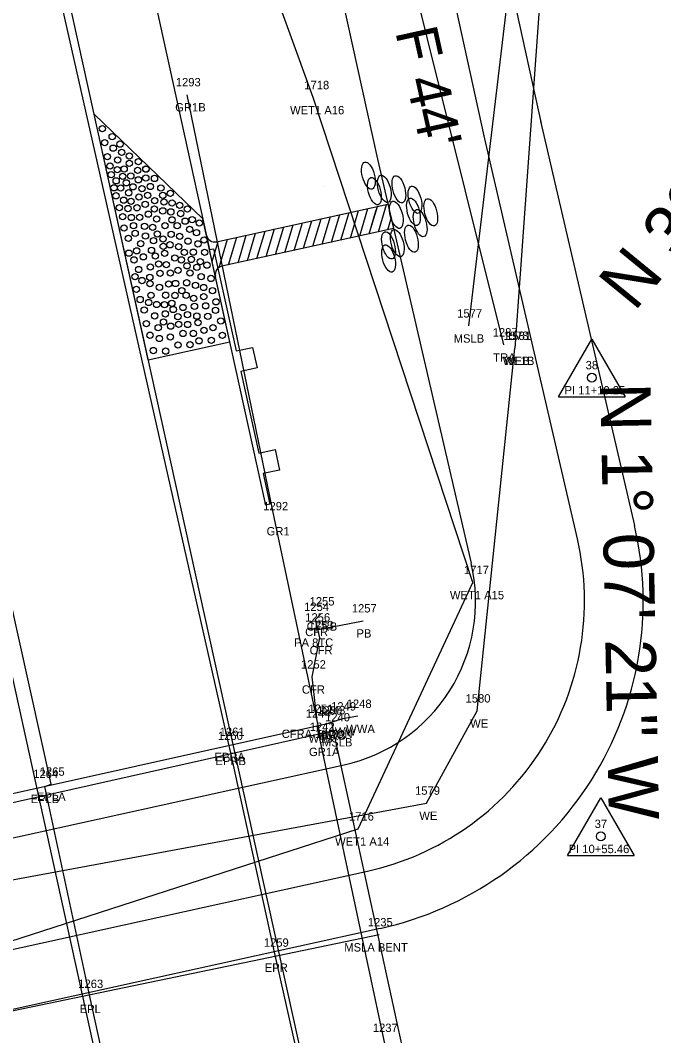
# Model space of a CAD drawing. Extents: x 2521558 to 2525396, y 882711 to 887632.
# Drawn here: x 2523767.9 to 2523844.7, y 885124.5 to 885245.8 of the extents above; entities that cross this region are included whole.
import ezdxf

# ---------------------------------------------------------------- set-up
doc = ezdxf.new("R2010")
doc.units = 0
for name, color, linetype in [('RD_EV_JurisArea', 7, 'Continuous'), ('RD_EX_BldgApp', 7, 'Continuous'), ('RD_EX_BldgApp_txCode', 7, 'Continuous'), ('RD_EX_Bridge', 7, 'Continuous'), ('RD_EX_Bridge_txCode', 7, 'Continuous'), ('RD_EX_Conc', 7, 'Continuous'), ('RD_EX_Conc_txCode', 7, 'Continuous'), ('RD_EX_DR_Pipe', 7, 'Continuous'), ('RD_EX_DR_Pipe_txCode', 7, 'Continuous'), ('RD_EX_GuardRail', 7, 'Continuous'), ('RD_EX_GuardRail_txCode', 7, 'Continuous'), ('RD_EX_H2O', 7, 'Continuous'), ('RD_EX_H2O_txCode', 7, 'Continuous'), ('RD_EX_H2O_WetLd_txCode', 7, 'Continuous'), ('RD_EX_Misc', 7, 'Continuous'), ('RD_EX_Misc_txCode', 7, 'Continuous'), ('RD_EX_Road', 7, 'Continuous'), ('RD_EX_Road_txCode', 7, 'Continuous'), ('RD_EX_VEG', 7, 'Continuous'), ('RD_EX_VEG_txCode', 7, 'Continuous'), ('RD_HC_Data', 7, 'Continuous'), ('RD_HC_txCode', 7, 'Continuous'), ('RD_PD_BCA', 7, 'Continuous'), ('RD_PD_Bridge', 7, 'Continuous'), ('RD_PD_CstnLmt', 7, 'Continuous'), ('RD_PD_DR_ErosCtrl', 7, 'Continuous'), ('RD_PD_Final_TrvlWay', 7, 'Continuous'), ('RD_PD_GR', 7, 'Continuous'), ('RD_PD_PaveShd', 7, 'Continuous'), ('RD_SMD_Locator', 7, 'Continuous')]:
    doc.layers.add(name, color=color, linetype=linetype)

# ---------------------------------------------------------------- blocks, each defined once
blk = doc.blocks.new('TBC1')
at = {"layer": 'RD_PD_GR'}
blk.add_lwpolyline([(12.5, 2.5), (15, 2.5), (15, 0.49), (25, 0.49), (25, 2.5), (27.5, 2.5), (27.5, 0.49), (31.25, 0.49), (31.25, 0), (0, 0), (0, 0.49), (12.5, 0.49)], close=True, dxfattribs=at)

msp = doc.modelspace()

# ---------------------------------------------------------------- linework, layer by layer
at = {"layer": 'RD_EV_JurisArea'}
msp.add_lwpolyline([(2523761.17, 885134.03), (2523808.21, 885149.21), (2523821.91, 885178.64), (2523802.85, 885236.55), (2523777.81, 885305.56), (2523748.2, 885444.32), (2523730.68, 885516.88), (2523708.64, 885617.3), (2523698.71, 885662.02), (2523727.83, 885665.82), (2523757.3, 885671.75)], dxfattribs=at)
at = {"layer": 'RD_EX_BldgApp'}
msp.add_lwpolyline([(2523819.44, 885087.44), (2523811.32, 885123.96), (2523803.31, 885161.5)], dxfattribs=at)
at = {"layer": 'RD_EX_Bridge'}
for points in [[(2523774.91, 885077.6), (2523821.2, 885087.83), (2523805.06, 885161.89), (2523758.15, 885151.44), (2523774.91, 885077.6)], [(2523808.19, 885162.66), (2523806.34, 885162.35), (2523804.71, 885161.86)]]:
    msp.add_lwpolyline(points, dxfattribs=at)
at = {"layer": 'RD_EX_Conc'}
msp.add_lwpolyline([(2523803.34, 885162.07), (2523802.73, 885167.36), (2523803.65, 885172.05), (2523803.12, 885174.24), (2523803.77, 885174.89)], dxfattribs=at)
at = {"layer": 'RD_EX_DR_Pipe'}
msp.add_line((2523803.27, 885172.97), (2523808.8, 885174.06), dxfattribs=at)
at = {"layer": 'RD_EX_GuardRail'}
msp.add_lwpolyline([(2523803.79, 885159.91), (2523798.24, 885186.26), (2523787.8, 885236.89)], dxfattribs=at)
at = {"layer": 'RD_EX_H2O'}
for points in [[(2524064.86, 885165.15), (2524036.37, 885213.78), (2524057.22, 885252.72), (2524031.95, 885291.63), (2523983.25, 885326.3), (2523940.61, 885311.83), (2523904.84, 885305.01), (2523874.98, 885272.1), (2523850.32, 885280.24), (2523830.66, 885258.8), (2523826.93, 885206.61)], [(2523738.91, 885147.5), (2523743.69, 885138.84), (2523816.36, 885152.29), (2523822.43, 885163.3), (2523826.93, 885206.61)]]:
    msp.add_lwpolyline(points, dxfattribs=at)
at = {"layer": 'RD_EX_Misc'}
for p, q in [((2523758.45, 885150.47), (2523805.66, 885161.06)), ((2523810.71, 885136.57), (2523763.83, 885126.8))]:
    msp.add_line(p, q, dxfattribs=at)
msp.add_lwpolyline([(2524066.31, 885165.35), (2524037.3, 885214.15), (2524057.95, 885253.07), (2524039.52, 885283.17), (2524032.92, 885292.57), (2523983.53, 885327.98), (2523940.24, 885313.27), (2523904.13, 885306.25), (2523874.86, 885272.67), (2523849.96, 885282.51), (2523827.65, 885261.93), (2523821.38, 885209.28)], dxfattribs=at)
at = {"layer": 'RD_EX_Road'}
for p, q in [((2523792.78, 885159.31), (2523771.24, 885254.79)), ((2523771.58, 885154.56), (2523750.32, 885250.18)), ((2523792.89, 885158.83), (2523792.78, 885159.31)), ((2523798.3, 885134.14), (2523792.89, 885158.83)), ((2523770.8, 885154.29), (2523771.58, 885154.56)), ((2523776.18, 885129.21), (2523770.8, 885154.29)), ((2523803.79, 885109.94), (2523798.3, 885134.14)), ((2523781.52, 885104.77), (2523776.18, 885129.21))]:
    msp.add_line(p, q, dxfattribs=at)
at = {"layer": 'RD_EX_VEG'}
msp.add_lwpolyline([(2523825.62, 885207.01), (2523811.87, 885262.11), (2523733.02, 885654.22), (2523687.11, 885876.24)], dxfattribs=at)
at = {"layer": 'RD_HC_Data'}
for p, q in [((2523832.14, 885200.81), (2523836.11, 885207.69)), ((2523836.11, 885207.69), (2523840.08, 885200.81)), ((2523832.14, 885200.81), (2523840.08, 885200.81)), ((2523833.21, 885146.03), (2523837.18, 885152.91)), ((2523837.18, 885152.91), (2523841.15, 885146.03)), ((2523833.21, 885146.03), (2523841.15, 885146.03))]:
    msp.add_line(p, q, dxfattribs=at)
for centre in [(2523836.11, 885203.1), (2523837.18, 885148.32)]:
    msp.add_circle(centre, 0.529, dxfattribs=at)
at = {"layer": 'RD_PD_BCA'}
for p, q in [((2523824.7, 885257.92), (2523830.05, 885233.47)), ((2523829.99, 885233.72), (2523841.2, 885185.45))]:
    msp.add_line(p, q, dxfattribs=at)
msp.add_lwpolyline([(2523762.05, 885126.6), (2523810.84, 885137.34)], dxfattribs=at)
msp.add_arc((2523802.24, 885176.4), 40, 282.4185, 13.0724, dxfattribs=at)
at = {"layer": 'RD_PD_CstnLmt'}
for p, q in [((2523789.14, 885326.89), (2523810.51, 885229.2)), ((2523810.51, 885229.2), (2523821.72, 885180.93))]:
    msp.add_line(p, q, dxfattribs=at)
msp.add_lwpolyline([(2523757.75, 885146.13), (2523806.54, 885156.87)], dxfattribs=at)
msp.add_arc((2523802.24, 885176.4), 20, 282.4185, 13.0724, dxfattribs=at)
at = {"layer": 'RD_PD_DR_ErosCtrl'}
for p, q in [((2523801.84, 885329.66), (2523823.21, 885231.97)), ((2523823.17, 885232.14), (2523834.38, 885183.87))]:
    msp.add_line(p, q, dxfattribs=at)
msp.add_lwpolyline([(2523760.55, 885133.43), (2523809.33, 885144.17)], dxfattribs=at)
msp.add_arc((2523802.24, 885176.4), 33, 282.4185, 13.0724, dxfattribs=at)
at = {"layer": 'RD_PD_Final_TrvlWay'}
for p, q in [((2523720.24, 885490.91), (2524037.44, 884050.42)), ((2523696.8, 885485.75), (2524014, 884045.26))]:
    msp.add_line(p, q, dxfattribs=at)
at = {"layer": 'RD_PD_GR'}
msp.add_line((2523742.1, 885438.13), (2523790.49, 885218.39), dxfattribs=at)
at = {"layer": 'RD_PD_PaveShd'}
for p, q in [((2523776.69, 885234.55), (2523789.68, 885222.05)), ((2523783.14, 885205.25), (2523776.69, 885234.55)), ((2523791.3, 885219.34), (2523811.76, 885223.83)), ((2523810.64, 885220.51), (2523811.62, 885223.8)), ((2523810.64, 885220.51), (2523811.62, 885223.8)), ((2523811.76, 885223.83), (2523812.44, 885220.91)), ((2523805.05, 885219.29), (2523806.04, 885222.57)), ((2523805.05, 885219.29), (2523806.04, 885222.57)), ((2523806.17, 885219.53), (2523807.15, 885222.82)), ((2523806.17, 885219.53), (2523807.03, 885222.41)), ((2523807.29, 885219.78), (2523808.27, 885223.06)), ((2523807.29, 885219.78), (2523808.27, 885223.06)), ((2523808.4, 885220.02), (2523809.39, 885223.31)), ((2523808.4, 885220.02), (2523809.39, 885223.31)), ((2523809.52, 885220.27), (2523810.51, 885223.55)), ((2523809.52, 885220.27), (2523810.38, 885223.15)), ((2523790.33, 885219.12), (2523789.68, 885222.05)), ((2523799.47, 885218.06), (2523800.45, 885221.35)), ((2523799.47, 885218.06), (2523800.45, 885221.35)), ((2523800.58, 885218.3), (2523801.57, 885221.59)), ((2523800.58, 885218.3), (2523801.57, 885221.59)), ((2523801.7, 885218.55), (2523802.68, 885221.84)), ((2523801.7, 885218.55), (2523802.68, 885221.84)), ((2523802.82, 885218.79), (2523803.8, 885222.08)), ((2523802.82, 885218.79), (2523803.8, 885222.08)), ((2523803.93, 885219.04), (2523804.92, 885222.33)), ((2523803.93, 885219.04), (2523804.92, 885222.33)), ((2523811.76, 885220.76), (2523812.16, 885222.1)), ((2523811.76, 885220.76), (2523812.16, 885222.1)), ((2523812.44, 885220.91), (2523791.95, 885216.41)), ((2523793.88, 885216.83), (2523794.86, 885220.12)), ((2523793.88, 885216.83), (2523794.86, 885220.12)), ((2523795, 885217.08), (2523795.98, 885220.36)), ((2523795, 885217.08), (2523795.98, 885220.36)), ((2523796.11, 885217.32), (2523797.1, 885220.61)), ((2523797.23, 885217.57), (2523798.22, 885220.86)), ((2523797.23, 885217.57), (2523798.22, 885220.86)), ((2523798.35, 885217.81), (2523799.33, 885221.1)), ((2523798.35, 885217.81), (2523799.33, 885221.1)), ((2523790.97, 885216.19), (2523790.33, 885219.12)), ((2523790.8, 885216.99), (2523791.51, 885219.38)), ((2523791.62, 885216.27), (2523792.63, 885219.63)), ((2523792.76, 885216.59), (2523793.75, 885219.87)), ((2523792.76, 885216.59), (2523793.75, 885219.87)), ((2523792.91, 885207.4), (2523790.97, 885216.19)), ((2523783.14, 885205.25), (2523792.91, 885207.4))]:
    msp.add_line(p, q, dxfattribs=at)
for centre in [(2523777.67, 885232.84), (2523778.86, 885231.88), (2523778.86, 885231.88), (2523777.97, 885231.17), (2523777.97, 885231.17), (2523778.98, 885230.51), (2523778.98, 885230.51), (2523779.79, 885230.99), (2523779.79, 885230.99), (2523778.28, 885229.5), (2523778.28, 885229.5), (2523779.98, 885230), (2523779.98, 885230), (2523780.9, 885229.57), (2523778.6, 885228.38), (2523778.6, 885228.38), (2523779.52, 885229.1), (2523779.52, 885229.1), (2523780.9, 885228.7), (2523780.9, 885228.7), (2523781.99, 885228.89), (2523781.99, 885228.89), (2523778.74, 885227.35), (2523778.74, 885227.35), (2523779.47, 885227.94), (2523779.47, 885227.94), (2523780.12, 885227.15), (2523780.12, 885227.15), (2523780.29, 885228.02), (2523780.29, 885228.02), (2523781.08, 885227.19), (2523781.08, 885227.19), (2523781.89, 885227.87), (2523781.89, 885227.87), (2523782.87, 885226.95), (2523782.87, 885226.95), (2523782.88, 885228.02), (2523782.9, 885228), (2523783.91, 885226.89), (2523783.91, 885226.89), (2523779.08, 885225.77), (2523779.08, 885225.77), (2523779.33, 885226.61), (2523779.33, 885226.61), (2523779.88, 885225.74), (2523779.88, 885225.74), (2523780.54, 885226.37), (2523780.54, 885226.37), (2523781.34, 885225.89), (2523781.34, 885225.89), (2523781.98, 885226.73), (2523781.98, 885226.73), (2523782.41, 885225.67), (2523782.41, 885225.67), (2523783.4, 885225.93), (2523783.4, 885225.93), (2523784.67, 885225.76), (2523784.67, 885225.76), (2523779.32, 885224.82), (2523779.32, 885224.82), (2523780.83, 885225.18), (2523780.83, 885225.18), (2523782.05, 885224.68), (2523782.05, 885224.68), (2523783.09, 885224.87), (2523783.09, 885224.87), (2523784.9, 885224.87), (2523784.9, 885224.87), (2523785.79, 885225.11), (2523785.8, 885225.11), (2523779.72, 885223.4), (2523779.72, 885223.4), (2523780.24, 885224.3), (2523780.24, 885224.3), (2523780.74, 885223.3), (2523780.74, 885223.3), (2523781.11, 885224.15), (2523781.11, 885224.15), (2523781.82, 885223.39), (2523781.82, 885223.39), (2523782.8, 885223.79), (2523782.8, 885223.79), (2523783.89, 885223.24), (2523783.89, 885223.24), (2523783.92, 885224.25), (2523783.92, 885224.25), (2523785.03, 885224.08), (2523785.03, 885224.08), (2523786.01, 885223.97), (2523786.01, 885223.97), (2523786.9, 885223.69), (2523786.9, 885223.69), (2523787.84, 885223.24), (2523787.84, 885223.24), (2523780.12, 885222.32), (2523780.12, 885222.32), (2523781.15, 885222.23), (2523781.15, 885222.23), (2523782.13, 885222.25), (2523782.13, 885222.25), (2523783.17, 885222.63), (2523783.17, 885222.63), (2523784.16, 885222.05), (2523784.16, 885222.05), (2523784.9, 885223.02), (2523784.9, 885223.02), (2523785.86, 885222.9), (2523785.86, 885222.9), (2523787.02, 885222.7), (2523787.02, 885222.7), (2523780.28, 885220.98), (2523780.28, 885220.98), (2523781.4, 885221.26), (2523781.4, 885221.26), (2523782.72, 885221.18), (2523782.72, 885221.18), (2523783.69, 885221.06), (2523783.69, 885221.06), (2523785.16, 885221.25), (2523785.16, 885221.25), (2523785.99, 885221.95), (2523785.99, 885221.95), (2523786.62, 885221.25), (2523786.62, 885221.25), (2523787.57, 885221.79), (2523787.57, 885221.79), (2523788.1, 885220.81), (2523788.1, 885220.81), (2523788.41, 885221.96), (2523788.41, 885221.96), (2523789.25, 885221.58), (2523789.25, 885221.58), (2523789.25, 885221.58), (2523780.79, 885219.73), (2523780.79, 885219.73), (2523781.6, 885220.34), (2523781.6, 885220.34), (2523782.83, 885220.03), (2523782.83, 885220.03), (2523784.24, 885220.27), (2523784.24, 885220.27), (2523784.93, 885219.66), (2523784.93, 885219.66), (2523785.9, 885220.22), (2523785.9, 885220.22), (2523786.92, 885219.97), (2523786.92, 885219.97), (2523788.92, 885220.42), (2523788.92, 885220.42), (2523789.82, 885219.55), (2523789.82, 885219.55), (2523782.26, 885219.11), (2523782.26, 885219.11), (2523783.79, 885219.46), (2523783.79, 885219.46), (2523784.95, 885218.78), (2523784.95, 885218.78), (2523785.75, 885218.97), (2523785.75, 885218.97), (2523786.79, 885218.75), (2523786.79, 885218.75), (2523787.91, 885219.4), (2523787.91, 885219.4), (2523789.1, 885219.08), (2523789.1, 885219.08), (2523780.85, 885217.97), (2523780.85, 885217.97), (2523781.47, 885217.17), (2523781.47, 885217.17), (2523781.78, 885218.25), (2523781.78, 885218.25), (2523782.57, 885217.53), (2523782.57, 885217.53), (2523783.55, 885218.31), (2523783.55, 885218.31), (2523784.01, 885217.64), (2523784.01, 885217.64), (2523785.12, 885217.95), (2523785.12, 885217.95), (2523786.34, 885217.39), (2523786.34, 885217.39), (2523787.1, 885217.17), (2523787.1, 885217.17), (2523787.47, 885218.08), (2523787.47, 885218.08), (2523788.31, 885217.22), (2523788.31, 885217.22), (2523788.55, 885218.09), (2523788.55, 885218.09), (2523789.89, 885218.08), (2523789.89, 885218.08), (2523782.02, 885216.02), (2523782.02, 885216.02), (2523783.41, 885216.33), (2523783.41, 885216.33), (2523784.4, 885216.67), (2523784.4, 885216.67), (2523785.31, 885216.59), (2523785.31, 885216.59), (2523786.72, 885215.92), (2523786.72, 885215.92), (2523787.79, 885216.46), (2523787.79, 885216.46), (2523788.96, 885216.29), (2523788.96, 885216.29), (2523789.37, 885216.96), (2523789.37, 885216.96), (2523790.18, 885216.54), (2523790.18, 885216.54), (2523781.59, 885215.16), (2523782.41, 885214.7), (2523782.41, 885214.7), (2523783.35, 885215.08), (2523783.35, 885215.08), (2523784.57, 885215.55), (2523784.57, 885215.55), (2523785.8, 885215.61), (2523785.8, 885215.61), (2523788.14, 885215.6), (2523788.14, 885215.6), (2523789.48, 885215.17), (2523789.48, 885215.17), (2523790.65, 885214.95), (2523790.65, 885214.95), (2523781.74, 885213.64), (2523781.74, 885213.64), (2523783.37, 885214.33), (2523783.37, 885214.33), (2523784.5, 885213.89), (2523784.5, 885213.89), (2523785.59, 885214.29), (2523785.59, 885214.29), (2523786.42, 885214.35), (2523786.42, 885214.35), (2523787.17, 885213.49), (2523787.17, 885213.49), (2523787.75, 885214.43), (2523787.75, 885214.43), (2523788.8, 885214.14), (2523788.8, 885214.14), (2523789.77, 885213.87), (2523789.77, 885213.87), (2523790.83, 885213.49), (2523790.83, 885213.49), (2523782.2, 885212.43), (2523782.2, 885212.43), (2523783.49, 885212.93), (2523783.49, 885212.93), (2523785.23, 885212.95), (2523785.23, 885212.95), (2523786.35, 885212.92), (2523786.35, 885212.92), (2523787.69, 885212.94), (2523787.69, 885212.94), (2523788.59, 885212.57), (2523788.59, 885212.57), (2523789.79, 885212.77), (2523789.79, 885212.77), (2523782.68, 885211.17), (2523782.68, 885211.17), (2523783.21, 885212.08), (2523783.21, 885212.08), (2523784.18, 885211.84), (2523784.18, 885211.84), (2523785.1, 885211.82), (2523785.1, 885211.82), (2523785.98, 885211.98), (2523785.98, 885211.98), (2523786.14, 885211.24), (2523787.3, 885211.48), (2523787.3, 885211.48), (2523788.68, 885211.63), (2523788.68, 885211.63), (2523790.02, 885211.68), (2523790.02, 885211.68), (2523791.19, 885211.15), (2523791.19, 885211.15), (2523791.25, 885212.16), (2523791.25, 885212.16), (2523783.94, 885210.48), (2523783.94, 885210.48), (2523785.21, 885210.72), (2523785.21, 885210.72), (2523786.7, 885210.38), (2523786.7, 885210.38), (2523787.85, 885210.63), (2523787.85, 885210.63), (2523788.96, 885210.45), (2523788.96, 885210.45), (2523790.27, 885210.43), (2523790.27, 885210.43), (2523791.82, 885209.86), (2523791.82, 885209.86), (2523782.94, 885209.56), (2523782.94, 885209.56), (2523784.35, 885209.08), (2523784.35, 885209.08), (2523784.98, 885209.75), (2523784.98, 885209.75), (2523785.85, 885209.25), (2523785.85, 885209.25), (2523786.79, 885209.46), (2523786.79, 885209.46), (2523787.87, 885209.45), (2523787.87, 885209.45), (2523789.11, 885209.66), (2523789.11, 885209.66), (2523789.81, 885208.75), (2523789.81, 885208.75), (2523790.88, 885209.07), (2523790.88, 885209.07), (2523783.37, 885208.17), (2523783.37, 885208.17), (2523784.48, 885207.78), (2523784.48, 885207.78), (2523785.79, 885207.95), (2523785.79, 885207.95), (2523787.3, 885208.38), (2523787.3, 885208.38), (2523788.54, 885208.38), (2523788.54, 885208.38), (2523789.21, 885207.5), (2523789.21, 885207.5), (2523790.7, 885207.57), (2523790.7, 885207.57), (2523792.01, 885208.15), (2523792.01, 885208.15), (2523792.01, 885208.15), (2523783.76, 885206.34), (2523783.76, 885206.34), (2523785.23, 885206.27), (2523785.23, 885206.27), (2523786.71, 885207.01), (2523786.71, 885207.01), (2523788.15, 885207.05), (2523788.15, 885207.05)]:
    msp.add_circle(centre, 0.375, dxfattribs=at)
for centre, start, end in [((2523791.09, 885220.31), 192.4185, 282.3889), ((2523792.16, 885215.43), 102.3889, 192.4185)]:
    msp.add_arc(centre, 1, start, end, dxfattribs=at)
for centre in [(2523809.44, 885227.23), (2523811.34, 885225.65), (2523811.34, 885225.65), (2523813.08, 885225.6), (2523813.08, 885225.6), (2523810.16, 885225.38), (2523815, 885224.35), (2523815, 885224.35), (2523812.77, 885222.55), (2523812.77, 885222.55), (2523814.82, 885222.91), (2523814.82, 885222.91), (2523816.89, 885222.85), (2523816.89, 885222.85), (2523815.62, 885221.56), (2523815.62, 885221.56), (2523814.58, 885219.7), (2523814.58, 885219.7), (2523811.84, 885218.9), (2523811.84, 885218.9), (2523812.89, 885219.17), (2523812.89, 885219.17), (2523811.85, 885217.33), (2523811.85, 885217.33)]:
    msp.add_ellipse(centre, major_axis=(-0.43, 1.62), ratio=0.429445, dxfattribs=at)
at = {"layer": 'RD_SMD_Locator'}
for centre in [(2523787.8, 885236.89), (2523802.85, 885236.55), (2523804.07, 885225.96), (2523821.38, 885209.28), (2523825.62, 885207.01), (2523826.93, 885206.61), (2523826.93, 885206.61), (2523836.11, 885203.1), (2523798.24, 885186.26), (2523821.91, 885178.64), (2523803.12, 885174.24), (2523803.77, 885174.89), (2523808.8, 885174.06), (2523803.27, 885172.97), (2523803.65, 885172.05), (2523802.73, 885167.36), (2523822.43, 885163.3), (2523803.34, 885162.07), (2523804.71, 885161.86), (2523805.06, 885161.89), (2523806.34, 885162.35), (2523808.19, 885162.66), (2523803.31, 885161.5), (2523805.66, 885161.06), (2523792.78, 885159.31), (2523803.79, 885159.91), (2523792.89, 885158.83), (2523771.58, 885154.56), (2523770.8, 885154.29), (2523816.36, 885152.29), (2523808.21, 885149.21), (2523837.18, 885148.32), (2523810.71, 885136.57), (2523798.3, 885134.14), (2523776.18, 885129.21)]:
    msp.add_circle(centre, 0.001, dxfattribs=at)

# ---------------------------------------------------------------- block references
at = {"layer": 'RD_PD_Bridge', "rotation": -77.58151740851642}
msp.add_blockref('TBC1', (2523790.49, 885218.39), dxfattribs=at)

# ---------------------------------------------------------------- texts
at = {"layer": 'RD_EX_BldgApp_txCode'}
for s, p in [('1244', (2523801.96, 885162.5)), ('W1B', (2523802.3, 885159.5)), ('1237', (2523809.97, 885124.96))]:
    msp.add_text(s, height=1, dxfattribs=at).set_placement(p)
at = {"layer": 'RD_EX_Bridge_txCode'}
for s, p in [('1249', (2523804.99, 885163.35)), ('1248', (2523806.85, 885163.66)), ('1250', (2523803.32, 885162.86)), ('1243', (2523803.72, 885162.89)), ('WWB', (2523803.33, 885159.86)), ('BRC', (2523803.81, 885159.89)), ('WW', (2523805.43, 885160.35)), ('WWA', (2523806.8, 885160.66))]:
    msp.add_text(s, height=1, dxfattribs=at).set_placement(p)
at = {"layer": 'RD_EX_Conc_txCode'}
for s, p in [('1255', (2523802.42, 885175.89)), ('1254', (2523801.77, 885175.24)), ('CFRB', (2523802.07, 885172.89)), ('1253', (2523802.3, 885173.05)), ('CFR', (2523801.89, 885172.24)), ('CFR', (2523802.42, 885170.05)), ('1252', (2523801.39, 885168.36)), ('CFR', (2523801.5, 885165.36)), ('1251', (2523802.28, 885163.07)), ('CFRA 18CON', (2523799.09, 885160.07))]:
    msp.add_text(s, height=1, dxfattribs=at).set_placement(p)
at = {"layer": 'RD_EX_DR_Pipe_txCode'}
for s, p in [('1257', (2523807.46, 885175.06)), ('1256', (2523801.9, 885173.97)), ('PB', (2523808.02, 885172.06)), ('PA 8TC', (2523800.57, 885170.97))]:
    msp.add_text(s, height=1, dxfattribs=at).set_placement(p)
at = {"layer": 'RD_EX_GuardRail_txCode'}
for s, p in [('1293', (2523786.45, 885237.89)), ('GR1B', (2523786.38, 885234.89)), ('1292', (2523796.89, 885187.26)), ('GR1', (2523797.29, 885184.26)), ('1242', (2523802.44, 885160.91)), ('GR1A', (2523802.35, 885157.91))]:
    msp.add_text(s, height=1, dxfattribs=at).set_placement(p)
at = {"layer": 'RD_EX_H2O_txCode'}
for s, p in [('1578', (2523825.58, 885207.61)), ('1581', (2523825.87, 885207.61)), ('WE1B', (2523825.47, 885204.61)), ('WEB', (2523825.64, 885204.61)), ('1580', (2523821.04, 885164.3)), ('WE', (2523821.59, 885161.3)), ('1579', (2523815.01, 885153.29)), ('WE', (2523815.52, 885150.29))]:
    msp.add_text(s, height=1, dxfattribs=at).set_placement(p)
at = {"layer": 'RD_EX_H2O_WetLd_txCode'}
for s, p in [('1718', (2523801.79, 885237.55)), ('WET1 A16', (2523800.09, 885234.55)), ('1717', (2523820.85, 885179.64)), ('WET1 A15', (2523819.17, 885176.64)), ('1716', (2523807.12, 885150.21)), ('WET1 A14', (2523805.47, 885147.21))]:
    msp.add_text(s, height=1, dxfattribs=at).set_placement(p)
at = {"layer": 'RD_EX_Misc_txCode'}
for s, p in [('1577', (2523820.04, 885210.28)), ('MSLB', (2523819.62, 885207.28)), ('1240', (2523804.27, 885162.06)), ('MSLB', (2523803.89, 885159.06)), ('1235', (2523809.37, 885137.57)), ('MSLA BENT', (2523806.56, 885134.57))]:
    msp.add_text(s, height=1, dxfattribs=at).set_placement(p)
at = {"layer": 'RD_EX_Road_txCode'}
for s, p in [('1260', (2523791.48, 885159.83)), ('1261', (2523791.69, 885160.31)), ('EPRA', (2523791.06, 885157.31)), ('EPRB', (2523791.19, 885156.83)), ('1264', (2523769.43, 885155.29)), ('1265', (2523770.21, 885155.56)), ('EPLB', (2523769.12, 885152.29)), ('EPLA', (2523769.88, 885152.56)), ('1259', (2523796.96, 885135.14)), ('EPR', (2523797.07, 885132.14)), ('1263', (2523774.81, 885130.21)), ('EPL', (2523774.97, 885127.21))]:
    msp.add_text(s, height=1, dxfattribs=at).set_placement(p)
at = {"layer": 'RD_EX_VEG_txCode'}
for s, p in [('1287', (2523824.28, 885208.01)), ('TRA', (2523824.34, 885205.01))]:
    msp.add_text(s, height=1, dxfattribs=at).set_placement(p)
at = {"layer": 'RD_HC_Data'}
for s, rotation, p in [('N 39%%d 17\' 08" E', 50.7144, (2523841.2, 885210.9)), ('N 1%%d 07\' 21" W', 271.1226, (2523837.12, 885202.44))]:
    msp.add_text(s, height=6, rotation=rotation, dxfattribs=at).set_placement(p)
at = {"layer": 'RD_HC_txCode'}
for s, p in [('38', (2523835.37, 885204.1)), ('PI 11+10.25', (2523832.85, 885201.1)), ('37', (2523836.45, 885149.32)), ('PI 10+55.46', (2523833.34, 885146.32))]:
    msp.add_text(s, height=1, dxfattribs=at).set_placement(p)
at = {"layer": 'RD_PD_CstnLmt'}
msp.add_text("F 44'", height=5, rotation=282.4185, dxfattribs=at).set_placement((2523812.63, 885244.45))

doc.saveas('drawing.dxf')
